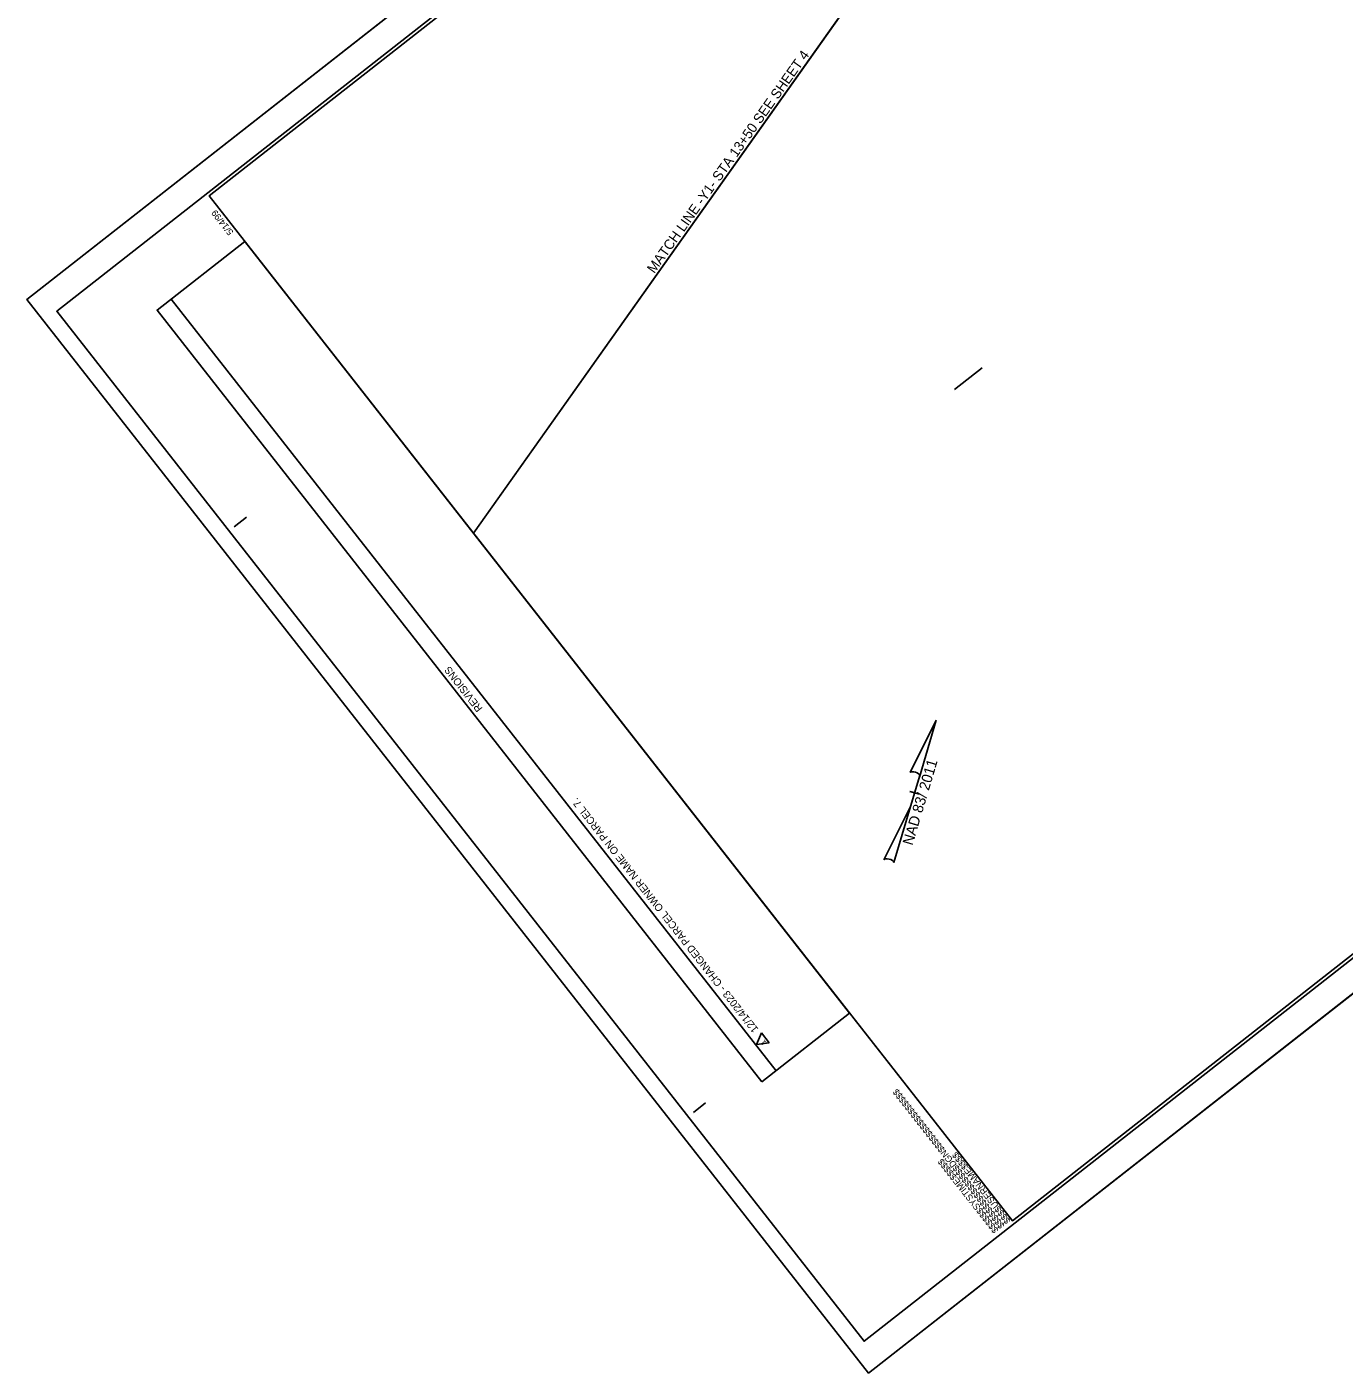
# Model space of a CAD drawing. Extents: x 2176242 to 2178501, y 76147 to 78096.
# Drawn here: x 2176242 to 2177304, y 76147 to 77232 of the extents above; entities that cross this region are included whole.
import ezdxf

# ---------------------------------------------------------------- set-up
doc = ezdxf.new("R2010")
doc.units = 0
for name, color, linetype in [('CTL Primary Horizontal and Vertical CELL', 7, 'Continuous'), ('CTL Primary Horizontal CELL', 7, 'Continuous'), ('CTL Primary Horizontal Cogo Elevation', 7, 'Continuous'), ('CTL Primary Horizontal Cogo Number', 7, 'Continuous'), ('Exist Other Culture Sign Cogo Point CELL', 7, 'Continuous'), ('Exist Roads EOP', 7, 'Continuous'), ('Exist Structure Minor Pipes RCP 18 Inch', 7, 'Continuous'), ('Exist Utilities Other Traffic Signal Box CELL', 7, 'Continuous')]:
    doc.layers.add(name, color=color, linetype=linetype)

msp = doc.modelspace()

# ---------------------------------------------------------------- linework, layer by layer
at = {"layer": 'CTL Primary Horizontal and Vertical CELL'}
msp.add_line((2176990.2, 76939.6), (2177012.4, 76957), dxfattribs=at)
msp.add_lwpolyline([(2176602.4, 76823.6), (2177302, 77811.1), (2177302, 77811.1), (2177306.5, 77814.6), (2177363.5, 77741.9), (2177469.3, 77824.8), (2177519.3, 77761), (2177676.8, 77884.4), (2178217.5, 77194.6), (2177036.9, 76269.2)], close=True, dxfattribs=at)
at = {"layer": 'CTL Primary Horizontal CELL'}
msp.add_lwpolyline([(2177578, 78030.7), (2176266.4, 77002.6), (2176917.3, 76172.2), (2178228.9, 77200.3)], close=True, dxfattribs=at)
at = {"layer": 'CTL Primary Horizontal Cogo Elevation'}
for p, q in [((2177567.7, 78051.1), (2176242.3, 77012.2)), ((2176920.9, 76146.5), (2178246.3, 77185.4)), ((2176242.3, 77012.2), (2176920.9, 76146.5))]:
    msp.add_line(p, q, dxfattribs=at)
at = {"layer": 'CTL Primary Horizontal Cogo Number'}
msp.add_lwpolyline([(2177567.7, 78051.1), (2176242.3, 77012.2), (2176920.9, 76146.5), (2178246.3, 77185.4)], close=True, dxfattribs=at)
at = {"layer": 'Exist Other Culture Sign Cogo Point CELL'}
for p, q in [((2176389.9, 77096.2), (2176389.9, 77096.2)), ((2176409.5, 76828.9), (2176419.4, 76836.6)), ((2176779.7, 76356.6), (2176789.5, 76364.4))]:
    msp.add_line(p, q, dxfattribs=at)
msp.add_lwpolyline([(2177569.7, 78021), (2176389.2, 77095.6), (2177036.9, 76269.2), (2178217.5, 77194.6)], close=True, dxfattribs=at)
at = {"layer": 'Exist Roads EOP'}
for p, q in [((2176954.3, 76630.7), (2176975.4, 76672.8)), ((2176975.4, 76672.8), (2176961.8, 76627)), ((2176975.4, 76672.8), (2176975.4, 76672.8)), ((2176975.4, 76672.8), (2176975.4, 76672.8)), ((2176954.7, 76603.2), (2176962.2, 76628.3)), ((2176961.8, 76627), (2176962.1, 76628.3)), ((2176954.2, 76615.5), (2176954.1, 76615.5)), ((2176954.2, 76615.5), (2176961.9, 76613.2)), ((2176957.6, 76614.5), (2176954.2, 76615.5)), ((2176954.7, 76603.2), (2176933.2, 76560.3)), ((2176941.3, 76558.1), (2176954.7, 76603.2))]:
    msp.add_line(p, q, dxfattribs=at)
for centre, start_param, end_param in [((2176958.1, 76629.1), 0.216388, 2.908219), ((2176937.2, 76559), 0.201328, 3.141593)]:
    msp.add_ellipse(centre, major_axis=(4.05, -1.24), ratio=0.461098, start_param=start_param, end_param=end_param, dxfattribs=at)
at = {"layer": 'Exist Structure Minor Pipes RCP 18 Inch'}
for p, q in [((2176846.4, 76390.3), (2176358.6, 77012.5)), ((2176830.6, 76411.4), (2176834.5, 76420.7)), ((2176840.6, 76412.9), (2176830.6, 76411.4)), ((2176840.6, 76412.9), (2176834.5, 76420.7))]:
    msp.add_line(p, q, dxfattribs=at)
msp.add_lwpolyline([(2176834.9, 76381.3), (2176347.2, 77003.6), (2176417.9, 77059), (2176905.6, 76436.7)], close=True, dxfattribs=at)
at = {"layer": 'Exist Utilities Other Traffic Signal Box CELL'}
msp.add_line((2176602.4, 76823.6), (2177302, 77811.1), dxfattribs=at)

# ---------------------------------------------------------------- texts
at = {"layer": 'Exist Other Culture Sign Cogo Point CELL'}
for s, p in [('5/14/99', (2176409.1, 77066.5)), ('$$$$$$$$$$$$$$$$DGN$$$$$$$$$$$$$$$$', (2177030.8, 76265.5)), ('$$$$USERNAME$$$$', (2177035.7, 76269.4)), ('$$$$$$SYSTIME$$$$$', (2177025.9, 76261.9))]:
    msp.add_text(s, height=5.25, rotation=128.091, dxfattribs=at).set_placement(p)
at = {"layer": 'Exist Roads EOP'}
msp.add_text('NAD 83/ 2011', height=8.5, rotation=73.406, dxfattribs=at).set_placement((2176956.2, 76571.5))
at = {"layer": 'Exist Structure Minor Pipes RCP 18 Inch'}
for s, height, p in [('REVISIONS', 6, (2176610, 76682.5)), ('  12/14/2023 - CHANGED PARCEL OWNER NAME ON PARCEL 7.', 6, (2176835.1, 76420.3)), (' 1', 4.5, (2176839.7, 76411.7))]:
    msp.add_text(s, height=height, rotation=128.091, dxfattribs=at).set_placement(p)
at = {"layer": 'Exist Utilities Other Traffic Signal Box CELL'}
msp.add_text('MATCH LINE -Y1- STA 13+50 SEE SHEET 4', height=8, rotation=54.6414, dxfattribs=at).set_placement((2176748.1, 77032.6))

doc.saveas('drawing.dxf')
